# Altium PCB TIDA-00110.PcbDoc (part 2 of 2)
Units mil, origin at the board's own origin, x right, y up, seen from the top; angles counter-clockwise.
Board outline 3543.31 x 1771.65 mil, 4 copper layers (Top Layer, L2_GND-PLANE, L3_PWR-PLANE, Bottom Layer), stack 90 mil thick; 191 components, 98 nets, 449 pads, 138 vias.
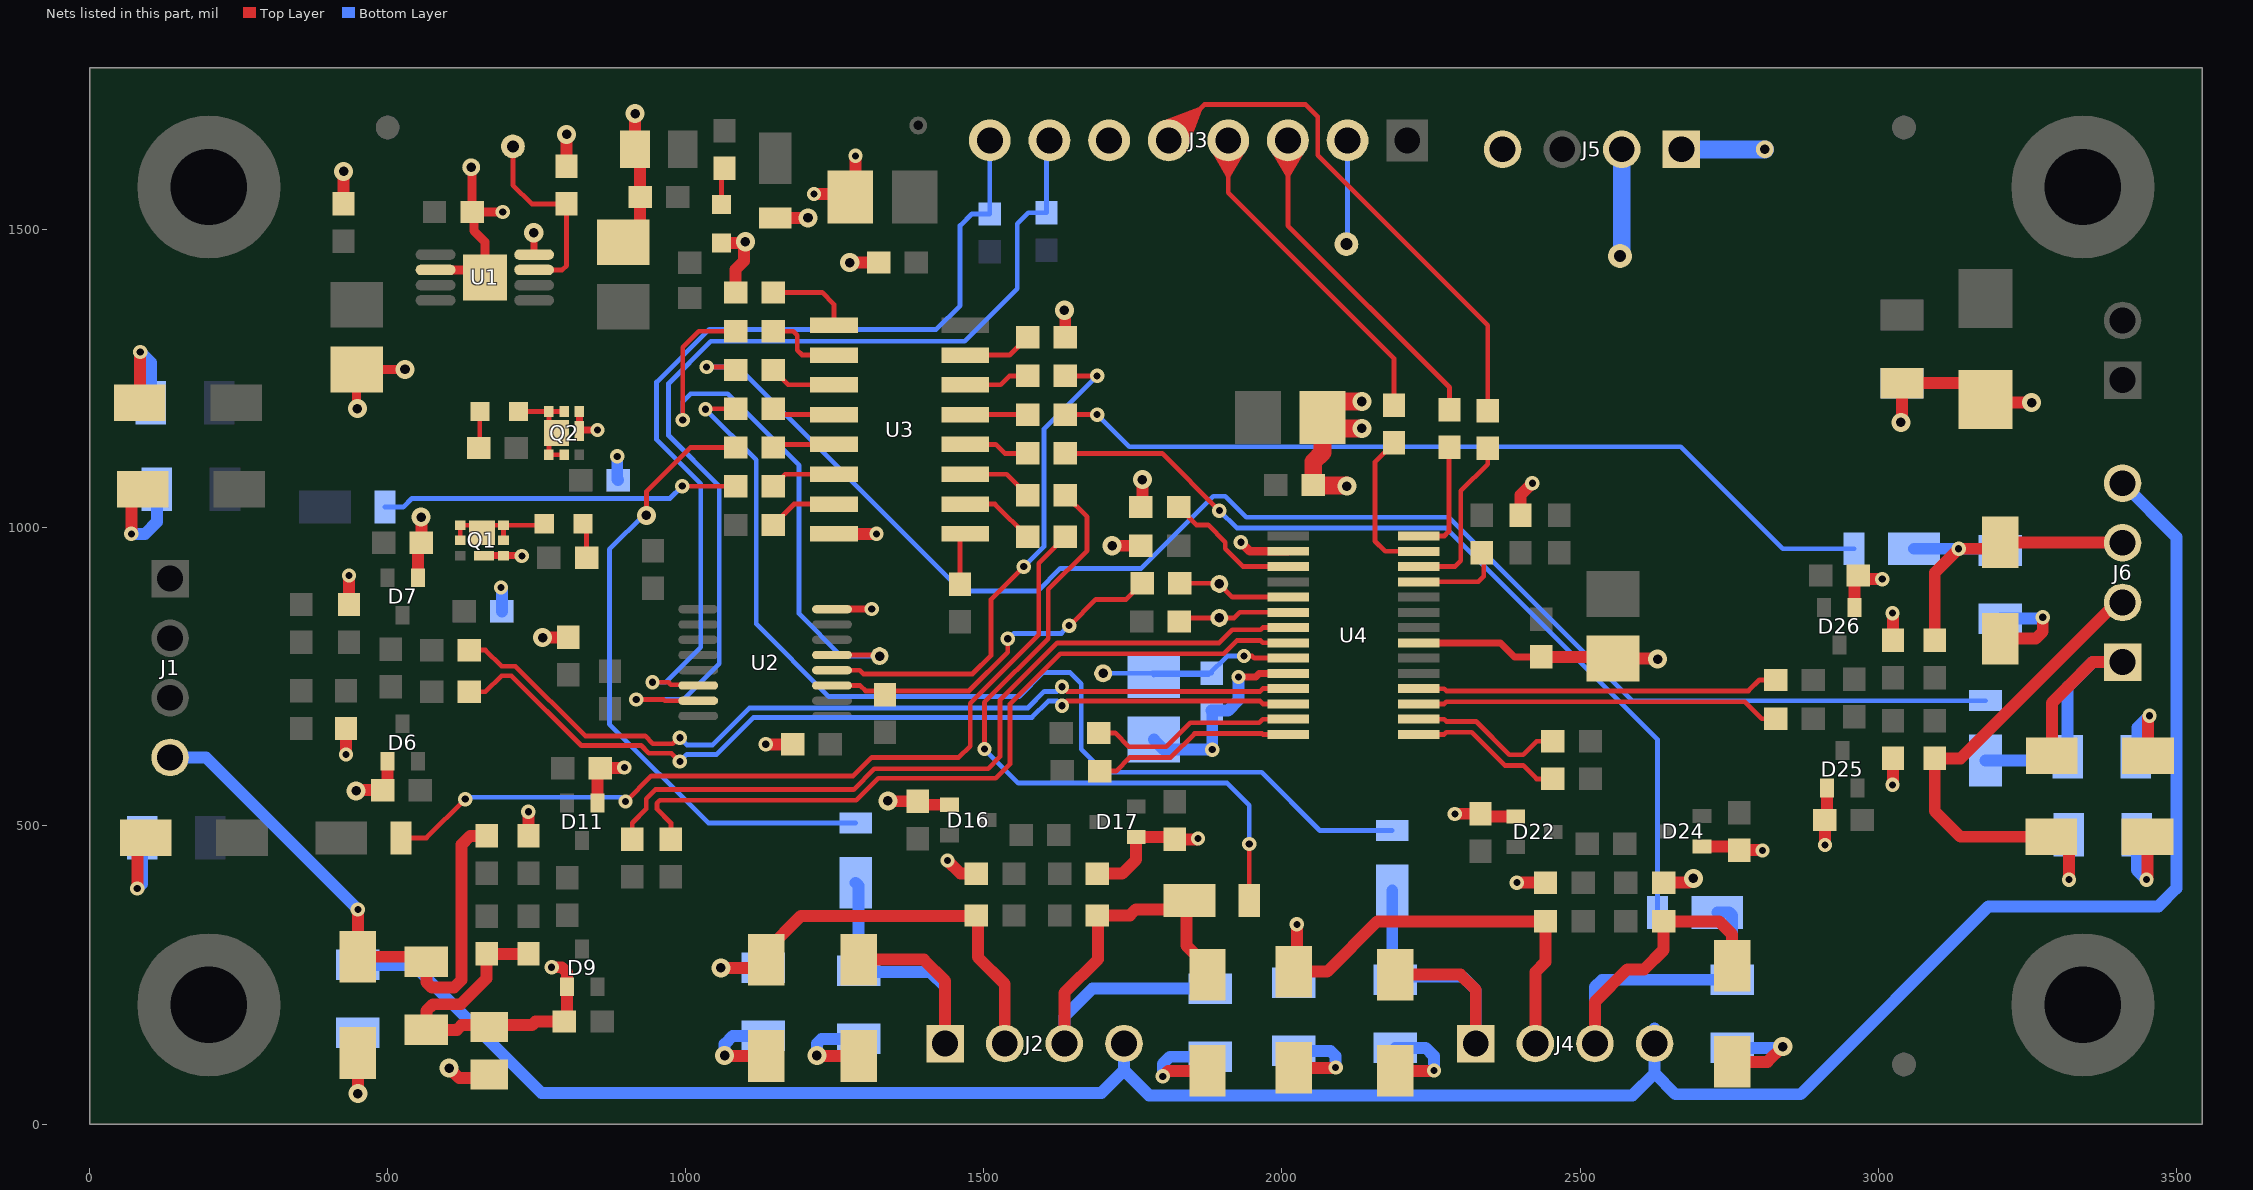
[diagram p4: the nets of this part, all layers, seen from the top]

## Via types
v1: diameter 24, hole 12, Top Layer to Bottom Layer, tented both sides, 92 vias
v2: diameter 32, hole 16, Top Layer to Bottom Layer, tented both sides, 45 vias
v3: diameter 36, hole 16, Top Layer to Bottom Layer, tented both sides, 1 vias

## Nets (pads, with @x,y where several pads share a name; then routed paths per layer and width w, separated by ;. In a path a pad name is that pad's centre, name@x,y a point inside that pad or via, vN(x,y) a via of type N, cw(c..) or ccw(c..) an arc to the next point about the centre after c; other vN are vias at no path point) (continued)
NetC46_1: C46.1 D12.2 J2.2 R28.2 | length 778.8
  Top Layer w20: v2(1059,262) 1121.29,262 D12.2@1135,275.71 1135,291 1193,349 1488.5,349 1490,347.5 1490,280 1535,235 J2.2@1535,135
  Bottom Layer w20: v2(1059,262) 1059.09,262.09 C46.1@1130,262.09
NetC47_2: C47.2 D15.1 D32.1 J2.1 | length 665.8
  Top Layer w20: D15.1@1290,275.71 1399.29,275.71 1435,240 J2.1@1435,135
  Bottom Layer w20: D32.1@1285,404.8 1290,399.8 C47.2@1290,257.09 1292.09,255 1410,255 1435,230 J2.1@1435,135
NetC48_1: C48.1 C50.1 TP5.1 U4.9 | length 427
  Top Layer w8: v1(1936.45,785) 1950,785 1953.4,781.6 U4.9@2010.5,781.6
  Bottom Layer w8: TP5.1@1700,756 C48.1@1782.13,756 ; C48.1@1785,753.13 C48.1@1784,754.13 ; C50.1@1882,756.5 1782.63,756.5 C48.1@1782.13,756 ; v1(1936.45,785) 1908,785 1877.13,754.13 C48.1@1784,754.13 ; C48.1@1782.13,756 C48.1@1784,754.13
NetC49_2: C49.2 D18.1 D19.1 J2.3 R30.2 | length 820.2
  Top Layer w20: J2.3@1635,135 1635,220 1691.5,276.5 R30.2@1691.5,350 ; R30.2@1690.5,350 R30.2@1691.5,350 ; D18.1@1839.8,365 D18.1@1839.8,352.2 ; D19.1@1875,264 1839.8,299.2 D18.1@1839.8,352.2 ; R30.2@1691.5,350 1745,350 1755,360 1832,360 D18.1@1839.8,352.2
  Bottom Layer w20: J2.3@1635,135 1635,180 1682.09,227.09 C49.2@1880,227.09
NetC51_1: C51.1 D20.2 J4.2 R45.2 | length 825.3
  Top Layer w20: v1(2025,335) 2025,260.71 D20.2@2020,255.71 2075.71,255.71 2160,340 R45.2@2442.01,340 2442.01,272.01 2425,255 J4.2@2425,160
  Bottom Layer w20: C51.1@2020,237.09 2025,242.09 v1(2025,335)
NetC53_2: C53.2 D21.1 D33.1 J4.1 | length 576.6
  Top Layer w20: D21.1@2190,250.71 2299.29,250.71 2325,225 J4.1@2325,160
  Bottom Layer w20: D33.1@2185,391.8 2185,247.09 C53.2@2190,242.09 2190,247.09 2302.91,247.09 2325,225 J4.1@2325,160
NetC54_2: C54.2 D23.1 D34.1 J4.3 R51.2 | length 860.2
  Top Layer w20: J4.3@2525,160 2525,205 2579.5,259.5 2607.5,259.5 2640,292 R51.2@2640,340 2733,340 2755,318 D23.1@2755,265.71
  Bottom Layer w20: J4.3@2525,160 2525,230 2537.09,242.09 C54.2@2755,242.09 2755,350 2750,355 D34.1@2730.2,355
NetC56_2: C56.2 D30.1 D35.1 J6.3 R55.2 | length 591.7
  Top Layer w20: R55.2@3095,811.5 3095,925 v1(3135,965) 3194.29,965 D30.1@3205,975.71 3409.29,975.71 J6.3@3410,975
  Bottom Layer w20: D35.1@3060.2,965 v1(3135,965) C56.2@3202.09,965
NetC57_1: C57.1 D27.2 J6.2 R54.2 | length 897.6
  Top Layer w20: v1(3320,410) 3320,475 3313,482 D27.2@3290.29,482 3138,482 3095,525 R54.2@3095,613.5 3138.5,613.5 3400,875 J6.2@3410,875
  Bottom Layer w20: C57.1@3319.91,485 3319.91,410.09 v1(3320,410)
NetC58_2: C58.2 D28.1 D36.1 J6.1 | length 602.4
  Top Layer w20: D28.1@3291.29,618 3291.29,706.29 3360,775 J6.1@3410,775
  Bottom Layer w20: D36.1@3180,609.8 3311.72,609.8 C58.2@3317.91,616 3317.91,732.91 3360,775 J6.1@3410,775
NetD8_1: D8.1 Q2.1 Q2.2 Q2.5 Q2.6 Q2.8 | length 166.9
  Top Layer w8: D8.1@719.8,1195.32 Q2.6@770.41,1195.32 ; Q2.8@770.41,1146.2 Q2.1@770.41,1122.68 Q2.2@796,1122.68 ; Q2.8@783.2,1159 770.41,1171.8 Q2.6@770.41,1195.32 ; Q2.5@796,1195.32 Q2.6@770.41,1195.32
NetD8_2: D8.2 R8.1 | length 59
  Top Layer w8: R8.1@654.52,1136.02 D8.2@654.52,1195
NetD10_1: D10.1 Q1.1 Q1.2 Q1.5 Q1.6 Q1.8 | length 210.4
  Top Layer w8: Q1.2@621.68,979 Q1.1@621.68,1004.59 645.2,1004.59 Q1.8@658,991.8 670.8,1004.59 Q1.6@694.32,1004.59 ; Q1.5@694.32,979 Q1.6@694.32,1004.59 ; D10.1@768.52,1009 764.11,1004.59 Q1.6@694.32,1004.59
NetD10_2: D10.2 R12.1 | length 59
  Top Layer w8: R12.1@833.5,950 D10.2@833.5,1008.98
NetD13_2: D13.2 R26.1 | length 63.1
  Top Layer w8: D13.2@1060,1542.48 1060,1598.5 R26.1@1065,1603.5
NetJ3_2: J3.2 TP8.1 | length 174.8
  Bottom Layer w8: TP8.1@2108,1476 2110,1478 J3.2@2110,1650
NetJ5_1: J5.1 TP10.1 | length 140
  Bottom Layer w30: J5.1@2670,1635 TP10.1@2810,1635
NetJ5_2: J5.2 TP9.1 | length 180.2
  Bottom Layer w30: TP9.1@2567,1456 2570,1459 J5.2@2570,1635
NetR14_2: R14.2 TP1.1 U1.3 | length 328.9
  Top Layer w8: TP1.1@710,1640 710,1575 741.5,1543.5 R14.2@800,1543.5 800,1440 792.8,1432.8 U1.3@745.68,1432.8
NetR19_2: R19.2 U3.6 | length 110.3
  Top Layer w8: R19.2@1146.5,1070 1166.5,1090 U3.6@1248.5,1090
NetR20_2: R20.2 U3.5 | length 104.1
  Top Layer w8: R20.2@1146.5,1135 1151.5,1140 U3.5@1248.5,1140
NetR21_2: R21.2 U3.4 | length 106.2
  Top Layer w8: R21.2@1146.5,1200 1156.5,1190 U3.4@1248.5,1190
NetR22_2: R22.2 U3.3 | length 112.4
  Top Layer w8: R22.2@1146.5,1265 1171.5,1240 U3.3@1248.5,1240
NetR23_2: R23.2 U3.2 | length 133.2
  Top Layer w8: R23.2@1146.5,1330 1180,1330 1187,1323 1187,1298 1195,1290 U3.2@1248.5,1290
NetR24_2: R24.2 U3.7 | length 116.5
  Top Layer w8: R24.2@1146.5,1005 1181.5,1040 U3.7@1248.5,1040
NetR25_1: R25.1 U3.1 | length 145.3
  Top Layer w8: R25.1@1146.5,1395 1228.5,1395 1248.5,1375 U3.1@1248.5,1340
NetR29_1: R29.1 U3.9 | length 85.2
  Top Layer w8: R29.1@1460,905.5 1460,957 U3.9@1460,981.5 ; U3.9@1468.5,990 U3.9@1475,983.5
NetR33_1: R33.1 U3.10 | length 127.8
  Top Layer w8: U3.10@1468.5,1040 1518.5,1040 R33.1@1573.5,985
NetR34_1: R34.1 U3.11 | length 119.5
  Top Layer w8: U3.11@1468.5,1090 1538.5,1090 R34.1@1573.5,1055
NetR35_1: R35.1 U3.12 | length 111.2
  Top Layer w8: U3.12@1468.5,1140 1520,1140 1535,1125 R35.1@1573.5,1125
NetR36_1: R36.1 U3.13 | length 105
  Top Layer w8: U3.13@1468.5,1190 R36.1@1573.5,1190
NetR37_1: R37.1 U3.14 | length 111.2
  Top Layer w8: U3.14@1468.5,1240 1528,1240 1543,1255 R37.1@1573.5,1255
NetR38_2: R38.2 U3.15 | length 117.4
  Top Layer w8: U3.15@1468.5,1290 1543.5,1290 R38.2@1573.5,1320
NetR39_2: R39.2 TP6.1 U4.6 | length 189.4
  Top Layer w8: R39.2@1827.5,843 1833.5,849 TP6.1@1895,849 1920,849 1929.4,858.4 U4.6@2010.5,858.4
NetR40_2: R40.2 TP7.1 U4.5 | length 191.5
  Top Layer w8: R40.2@1828.5,907 1894,907 TP7.1@1895,906 1917,884 U4.5@2010.5,884
NetR41_1: R41.1 U4.3 | length 231.8
  Top Layer w8: R41.1@1826.5,1035 1856.5,1005 1876,1005 1905,976 1905,965 1934.8,935.2 U4.3@2010.5,935.2
NetR42_1: R42.1 U4.25 | length 152.7
  Top Layer w8: U4.25@2229.5,909.5 2289.5,909.5 2329.5,909.5 2338.5,918.5 R42.1@2338.5,958.5
NetR43_1: R43.1 U4.27 | length 258.4
  Top Layer w8: R43.1@2188,1142.5 2156,1110.5 2156,978 2173.3,960.7 U4.27@2229.5,960.7
NetR44_1: R44.1 U4.28 | length 195.6
  Top Layer w8: U4.28@2229.5,986.4 2272.4,986.4 2280,994 2280,1134.5 R44.1@2281,1135.5
NetR47_1: R47.1 U4.26 | length 281.7
  Top Layer w8: U4.26@2229.5,935.1 2290.1,935.1 2300,945 2300,1062 2345,1107 R47.1@2345,1133.5
RATIO: C43.2 D4.1 J1.4 J2.4 J4.4 J6.4 R3.2 R10.2 | length 5280.8
  Top Layer w20: v1(450,360) D4.1@450,280.71 556.38,280.71 R3.2@565,272.09 565,238 574,229 611,229 624,242 624,469 638.5,483.5 R10.2@666,483.5 ; J6.4@3400,1075 J6.4@3410,1075
  Bottom Layer w20: J1.4@135,615 195,615 v1(450,360) C43.2@450,267.09 542.91,267.09 757.68,52.32 1697.32,52.32 1735,90 ; J2.4@1735,135 1735,90 ; J4.4@2625,160 2625,85 ; J6.4@3410,1075 3500.31,984.69 3500.31,395.31 3470,365 3185,365 2870,50 2660,50 2625,85 ; 1735,90 1777,48 2588,48 2625,85
RESET1: R27.1 R40.1 U2.3 | length 612.1
  Top Layer w8: U2.3@1245.2,735.61 1292.39,735.61 1301.5,726.5 1475.05,726.5 1540,791.45 v1(1540,814) ; v1(1643,836) 1644,836 1688,880 1738.5,880 R40.1@1765.5,907
  Bottom Layer w8: v1(1540,814) 1541,814 1550,823 1630,823 v1(1643,836)
RTD1_IEXC1: D31.2 R19.1 | length 602.8
  Top Layer w8: v1(994,1070) R19.1@1083.5,1070
  Bottom Layer w8: D31.2@495.2,1035 526,1035 540.3,1049.3 973.3,1049.3 v1(994,1070)
RTD1_IEXC2: D5.2 R33.2 | length 1436.6
  Top Layer w8: D5.2@522.2,480 565,480 v1(630,545) ; v1(899,541) 942,584 1281,584 1312,615 1458,615 1477,634 1477,705.82 1592.09,820.91 1592.09,940.59 R33.2@1636.5,985
  Bottom Layer w8: v1@634,549 635,548 892,548 v1(899,541)
RTD2_IEXC1: D32.2 R20.1 | length 1083.5
  Top Layer w8: v2(934,1021) 934,1061 1008,1135 R20.1@1083.5,1135
  Bottom Layer w8: v2(934,1021) 934,1022 932,1024 872,964 872,671 1037.8,505.2 D32.2@1285,505.2
RTD2_IEXC2: D18.2 R34.2 | length 1155.4
  Top Layer w8: v1(1501,629) 1501,707.2 1608.09,814.28 1608.09,897.09 1673,962 1673,1018.5 R34.2@1636.5,1055 ; D18.2@1945.2,375 v1(1945.2,469.8)
  Bottom Layer w8: v1(1501,629) 1558,572 1908,572 1945.2,534.8 v1(1945.2,469.8)
RTD3_IEXC1: D33.2 R21.1 | length 1754.8
  Top Layer w8: v1(1033,1199) 1034,1200 R21.1@1083.5,1200
  Bottom Layer w8: v1(1033,1199) 1118,1114 1118,839 1240,717 1559,717 1599.6,757.6 1644.4,757.6 1663.4,738.6 1663.4,628.6 1702,590 1966,590 2063.8,492.2 D33.2@2185,492.2
RTD3_IEXC2: D34.2 R35.2 | length 1482.2
  Top Layer w8: R35.2@1636.5,1125 1799,1125 v1(1895,1029)
  Bottom Layer w8: v1(1895,1029) 1924,1000 2275,1000 2629.8,645.2 D34.2@2629.8,355
RTD4_IEXC1: D36.2 R22.1 | length 2559.2
  Top Layer w8: v1(1035,1270) 1078.5,1270 R22.1@1083.5,1265
  Bottom Layer w8: v1(1035,1270) 1087,1270 1463,894 1590,894 1628,932 1764,932 1885,1053 1904.94,1053 1939.94,1018 2279.63,1018 2587.43,710.2 D36.2@3180,710.2
RTD4_IEXC2: D35.2 R36.2 | length 1416.5
  Top Layer w8: R36.2@1636.5,1190 v1(1690,1190)
  Bottom Layer w8: v1(1690,1190) 1744,1136 2669,1136 2840,965 D35.2@2959.8,965
RTD_AINN1: R6.1 U4.12 | length 1495.5
  Top Layer w8: R6.1@636.5,725 664,725 691,752 707.54,752 824.54,635 925,635 938,622 976,622 v1(990,608) ; v1(1631,701.6) 1639,709.6 1963.2,709.6 1968,704.8 U4.12@2010.5,704.8
  Bottom Layer w8: v1(990,608) 1002,620 1051.63,620 1113.63,682 1580.63,682 1608.23,709.6 1623,709.6 v1(1631,701.6)
RTD_AINN2: R31.1 U4.14 | length 342.7
  Top Layer w8: R31.1@1694.5,592 1722,592 1745,615 1813.46,615 1853.46,655 1966.6,655 1968,653.6 U4.14@2010.5,653.6
RTD_AINN3: R49.1 U4.16 | length 259
  Top Layer w8: U4.16@2229.5,679.1 2272,679.1 2275.8,675.3 2325.46,675.3 2381.26,619.5 2404.5,619.5 2427,642 R49.1@2454.5,642
RTD_AINN4: R53.1 U4.18 | length 608.2
  Top Layer w8: U4.18@2229.5,730.3 2272,730.3 2275.8,726.5 2782.5,726.5 2801,745 R53.1@2828.5,745
RTD_AINP1: R5.1 U4.11 | length 1493.9
  Top Layer w8: R5.1@636.5,795 664,795 691,768 714.17,768 831.17,651 931.63,651 944.63,638 978,638 988,648 v1(990,648) ; v1(1631,733.6) 1639,725.6 1963.2,725.6 1968,730.4 U4.11@2010.5,730.4
  Bottom Layer w8: v1(990,648) 1002,636 1045,636 1107,698 1574,698 1601.6,725.6 1623,725.6 v1(1631,733.6)
RTD_AINP2: R32.1 U4.13 | length 346.7
  Top Layer w8: R32.1@1692.5,656 1720,656 1743,633 1806,633 1846,673 1961.8,673 1968,679.2 U4.13@2010.5,679.2
RTD_AINP3: R48.1 U4.15 | length 259
  Top Layer w8: U4.15@2229.5,653.5 2272,653.5 2275.8,657.3 2318,657.3 2373.8,601.5 2404.5,601.5 2427,579 R48.1@2454.5,579
RTD_AINP4: R52.1 U4.17 | length 612.4
  Top Layer w8: U4.17@2229.5,704.7 2272,704.7 2275.8,708.5 2776.5,708.5 2805,680 R52.1@2828.5,680
RTD_REFN0: R17.1 U4.8 | length 1303
  Top Layer w8: R17.1@975,477.5 975,505 951.5,528.5 951.5,538 956.5,543 1286,543 1323,580 1520,580 1544,604 1544,704.94 1628.06,789 1902,789 1924,811 1964.2,811 1968,807.2 U4.8@2010.5,807.2
RTD_REFP0: R15.1 U4.7 | length 1329.1
  Top Layer w8: R15.1@910,477.5 910,505 933.5,528.5 933.5,545.46 949.04,561 1281.37,561 1316.37,596 1507,596 1527,616 1527,710.57 1623.43,807 1894.54,807 1916.54,829 1964.2,829 1968,832.8 U4.7@2010.5,832.8
RTD_SEL0: R37.2 U2.4 | length 878.4
  Top Layer w8: U2.4@1245.2,761.2 1291.8,761.2 1298,755 1480.92,755 1512,786.08 1512,880 v1(1567,935) ; R37.2@1636.5,1255 v1(1690,1255)
  Bottom Layer w8: v1(1567,935) 1601,969 1601,1166 v1(1690,1255)
RTD_SEL1: R23.1 TP3.1 U2.5 | length 1000.3
  Top Layer w8: v1(995,1181) 995,1303 1022,1330 R23.1@1083.5,1330 ; U2.5@1245.2,786.8 1323.2,786.8 TP3.1@1325,785
  Bottom Layer w8: v1(995,1181) 995,1212 1008,1225 1070,1225 1190,1105 1190,856 1261,785 TP3.1@1325,785 ; TP3.1@1332.5,790.5 TP3.1@1335,788
SCL: J3.8 R56.1 U2.14 | length 1537.5
  Top Layer w8: v1(944,741) 971,741 975,737 1019.41,737 U2.14@1020.8,735.61
  Bottom Layer w8: v1(944,741) 966,741 1025,800 1025,1074 951,1148 951,1244.63 1039.37,1333 1420,1333 1460,1373 1460,1507 1479.5,1526.5 R56.1@1510,1526.5 J3.8@1510,1650
SCLK: J3.3 R44.2 | length 1036.1
  Top Layer w8: J3.3@1980.05,1641.84 2010,1590.96 ; J3.3@1987.4,1645.5 2010,1590.96 ; J3.3@1995.08,1648.08 2010,1590.96 ; J3.3@2002.97,1649.58 2010,1590.96 ; J3.3@2010,1650 2010,1507 2281,1236 R44.2@2281,1198.5 ; J3.3@2017.03,1649.58 2010,1590.96 ; J3.3@2024.92,1648.08 2010,1590.96 ; J3.3@2032.6,1645.5 2010,1590.96 ; J3.3@2039.95,1641.84 2010,1590.96
SDA: J3.7 R57.1 U2.15 | length 1713.8
  Top Layer w8: v1(917,712) 963.02,712 965,710.02 U2.15@1020.8,710.02
  Bottom Layer w8: v1(917,712) 996,712 1056,772 1056,1070 971,1155 971,1242 1042,1313 1468,1313 1556,1401 1556,1510 1574.5,1528.5 R57.1@1605,1528.5 1605,1645 J3.7@1610,1650
SDI: J3.5 R47.2 | length 1483.1
  Top Layer w8: J3.5@1793.18,1676.09 1862.01,1702.01 ; J3.5@1796.46,1668.64 1862.01,1702.01 ; J3.5@1800.51,1661.67 1862.01,1702.01 ; J3.5@1805.27,1655.21 1862.01,1702.01 ; J3.5@1810,1650 1870,1710 2040,1710 2060,1690 2060,1625 2345,1340 R47.2@2345,1196.5 ; J3.5@1815.21,1645.27 1862.01,1702.01 ; J3.5@1821.67,1640.51 1862.01,1702.01 ; J3.5@1828.64,1636.46 1862.01,1702.01 ; J3.5@1836.09,1633.18 1862.01,1702.01
SDO: J3.4 R43.2 | length 1032
  Top Layer w8: J3.4@1880.05,1641.84 1910,1590.96 ; J3.4@1887.4,1645.5 1910,1590.96 ; J3.4@1895.08,1648.08 1910,1590.96 ; J3.4@1902.97,1649.58 1910,1590.96 ; J3.4@1910,1650 1910,1562 2188,1284 R43.2@2188,1205.5 ; J3.4@1917.03,1649.58 1910,1590.96 ; J3.4@1924.92,1648.08 1910,1590.96 ; J3.4@1932.6,1645.5 1910,1590.96 ; J3.4@1939.95,1641.84 1910,1590.96
SGND: C2.2 C3.1 C4.2 C5.2 C6.2 C7.2 C8.1 C9.2 C10.1 C11.2 C13.2 C14.2 C15.1 C16.2 C17.2 C18.2 C19.2 C20.2 C21.1 C22.2 C24.2 C25.2 C26.2 C27.2 C28.1 C29.2 C31.2 C32.2 C33.2 C35.2 C36.2 C37.1 C38.2 C44.2 C45.2 C48.2 C50.2 C52.2 D6.1 D7.1 D9.1 D11.1 D13.1 D14.2 D16.1 D17.1 D22.1 D24.1 D25.1 D26.1 J3.6 J5.4 Q1.4 Q1.7 Q2.4 Q2.7 R3.1 R4.2 R9.2 R11.1 R14.1 R25.2 R38.1 R41.2 R46.1 TP2.1 U1.4 U1.6 U1.9 U2.8 U3.8 U4.2 U4.10 U4.21 | length 5008.7
  Top Layer w12: Q1.7@661.78,953.41 Q1.4@694.32,953.41 717.59,953.41 724,947 725,948 v1(725,953) ; v2(745,1495) 745.68,1494.32 U1.4@745.68,1458.39 ; Q2.7@821.59,1162.78 Q2.4@821.59,1195.32 ; Q2.7@822.59,1164.32 v1(852,1164.32) v1@855.68,1164.32 ; C14.2@893.39,1458.39 C14.2@900,1465 ; U2.8@1245.2,863.57 1245.64,864 v1(1312,864) ; v1(1927,750) 1956,750 1962,756 U4.10@2010.5,756 ; U4.21@2229.5,807.1 2366.4,807.1 2390,783.5 C29.2@2435,783.5
  Top Layer w15: v2(449,1200) 448,1201 C4.2@448,1265.87 528.87,1265.87 v2(529,1266) ; U1.6@580.32,1432.8 U1.9@650.2,1432.8 ; C8.1@641.5,1530 641.5,1596.5 TP2.1@645,1600 ; U1.9@663,1420 663,1480 644.5,1498.5 644.5,1530 v1(693,1530) ; v1(1931,976) 1946.2,960.8 U4.2@2010.5,960.8
  Top Layer w20: C5.2@426,1543.5 v2(426,1598) ; v1(430,620) C2.2@430,663.5 ; C3.1@435,871.5 v1(435,920) ; v2(447,559) 448,560 C6.2@491.5,560 499.41,567.91 D6.1@499.41,608.5 ; D7.1@550.59,916.5 C7.2@550.59,969.09 ; v2(556,1018) 556.5,1017.5 C7.2@556.5,975 ; C9.2@736,285.5 R4.2@666,285.5 666,244.4 622.6,201 576,201 565,190 R3.1@565,157.91 615.91,157.91 624,166 742,166 748,172 C11.2@796.5,172 ; C10.1@736,483.5 v1(736,524) ; v2(760,816) 760.5,816.5 R11.1@803,816.5 ; v1(775,263) 792,263 800.41,254.59 D9.1@800.41,230.5 C11.2@800.41,175.91 ; R14.1@800,1606.5 v2(800,1660) ; D11.1@851.59,538.5 C13.2@851.59,592.09 ; C13.2@856.5,597 896,597 v1(897,598) ; C14.2@895,1479.13 923.5,1507.64 C15.1@923.5,1555 923.5,1626.5 C16.2@915,1635 v2@915,1690 ; D13.1@1055,1477.52 D13.1@1060,1477.52 1097.52,1477.52 1097.52,1447.52 1083.5,1433.5 R25.2@1083.5,1395 ; v1(1134,637) C17.2@1179.5,637 ; D14.2@1150,1519.8 1204.8,1519.8 v2(1205,1520) ; v1(1215,1560) 1248,1560 1250,1558 1284.87,1558 1284.87,1623.87 v1(1284.73,1624) ; U3.8@1248.5,990 v1(1320,990) ; v2(1275,1445) C19.2@1323.5,1445 ; v2(1339,542) 1339.5,541.5 C18.2@1389,541.5 ; C18.2@1394.91,535.59 D16.1@1442.5,535.59 ; v1(1439,442) 1461,420 C21.1@1487.5,420 ; v2(1635,1365) 1636.5,1363.5 R38.1@1636.5,1320 ; C22.2@1690.5,420 1732,420 1755.5,443.5 D17.1@1755.5,481.41 1816.09,481.41 C24.2@1820,477.5 1857.5,477.5 v1(1859,479) ; v2(1715,970) C25.2@1763.5,970 ; R41.2@1763.5,1035 1766,1037.5 v2(1766,1081) ; v1(2290,520) 2290.5,520.5 C27.2@2333,520.5 2337.91,515.59 D22.1@2392.01,515.59 ; v1(2394,405) C28.1@2442.01,405 ; R46.1@2400,1021.5 2400,1055 v1(2420,1075) ; C29.2@2435,783.5 C31.2@2552.36,783.5 ; C31.2@2555,780.87 2629.13,780.87 v2(2630,780) ; C32.2@2640,405 2683,405 v2(2690,412) ; D24.1@2704.5,465.41 C33.2@2761.09,465.41 ; C33.2@2767,459.5 2805.5,459.5 v1(2806,459) ; C35.2@2910.5,510 2910.5,468.5 v1(2911,468) ; C35.2@2914.41,513.91 D25.1@2914.41,563.5 ; D26.1@2960.59,866.5 2960.59,914.09 2960.68,914 v1(3007,914) ; v1(3024,569) 3025,568 C37.1@3025,613.5 ; v1(3024,857) 3025,856 C38.2@3025,811.5
  Top Layer w30: v2(2109,1070) 2108,1071 2052.5,1071 C52.2@2052.5,1072 2052.5,1111 2068.13,1126.64 C26.2@2068.13,1185 ; v2(2134,1167) 2086.13,1167 C26.2@2068.13,1185 ; v2(2134,1212) 2095.13,1212 C26.2@2068.13,1185
  Bottom Layer w20: v1(690,900) 691.5,898.5 C44.2@691.5,860 ; v1(885,1120) 885,1081.5 C45.2@886.5,1080 ; C48.2@1785,644.87 1801.87,628 v1(1883,628) C50.2@1883,693.5 ; C50.2@1882,693.5 C50.2@1883,693.5 ; v1(1927,750) 1927,711 1909.5,693.5 C50.2@1883,693.5
  other v2: 1100,1480 915,1695
SGND1: C39.1 C40.1 C41.1 C42.2 C43.1 C46.2 C47.1 C49.1 C51.2 C53.1 C54.1 C55.1 C56.1 C57.2 C58.1 D1.2 D2.2 D3.1 D4.2 D12.1 D15.2 D19.2 D20.1 D21.2 D23.2 D27.1 D28.2 D29.1 D30.2 R9.1 | length 2646.2
  Top Layer w20: v1(70,990) 70,1045.71 D2.2@89.29,1065 ; v1(80,395) 80,465.71 D1.2@94.29,480 ; D3.1@84.29,1210 84.29,1294.29 v1(85,1295) ; v2(450,51) 449,52 449,58 450,59 D4.2@450,119.29 ; v2(603,94) 620,77 652,77 R9.1@670,95 ; v2(1065,115) 1065.71,114.29 D12.1@1135,114.29 ; v2(1220,115) 1220.71,114.29 D15.2@1290,114.29 ; v1(1800,80) 1809.29,89.29 D19.2@1875,89.29 ; D20.1@2020,94.29 2089.29,94.29 v1(2090,95) ; D21.2@2190,89.29 2254.29,89.29 v1(2255,90) ; D23.2@2755,104.29 2814.29,104.29 v2(2840,130) ; v2@3040,1179 C39.1@3040,1242.91 3152.44,1242.91 D29.1@3180,1215.35 3185.31,1210.04 v2(3257.56,1210.04) ; D30.2@3205,814.29 3264.29,814.29 3276.14,826.14 v1(3276.14,850) ; v1(3450,410) 3451.71,411.71 D27.1@3451.71,482 ; D28.2@3452.71,618 3452.71,682.71 v1(3455,685)
  Bottom Layer w20: v1(70,990) 93,990 112.91,1009.91 C41.1@112.91,1065 ; v1(80,395) 87.91,402.91 C40.1@87.91,480 ; v1(85,1295) 102.91,1277.09 C42.2@102.91,1210 ; v2(450,51) C43.1@450,152.91 ; v2(1065,115) 1065,134.09 1078.83,147.91 C46.2@1130,147.91 ; v2(1220,115) 1220,135 1227.91,142.91 C47.1@1290,142.91 ; v1(1800,80) 1800,101 1811.91,112.91 C49.1@1880,112.91 ; C51.2@2020,122.91 2081.09,122.91 2090,114 v1(2090,95) ; C53.1@2190,127.91 2241.09,127.91 2255,114 v1(2255,90) ; C54.1@2755,127.91 2837.91,127.91 v2(2840,130) ; v2(3038,1177) 3040,1179 C55.1@3040,1242.91 ; C56.1@3205,847.91 3274.06,847.91 v1(3276.14,850) ; C58.1@3432.09,616 3435,618.91 3435,665 v1(3455,685) ; C57.2@3434.09,485 3434.09,425.91 v1(3450,410)
pads on no net: FID1.1 FID2.1 FID3.1 FID4.1 FID5.1 FID6.1 H1.1 H2.1 H3.1 H4.1 J3.1 U1.2

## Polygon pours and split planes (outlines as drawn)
SGND1 on L2_GND-PLANE "Bottom Layer-No Net" (solid, remove dead copper, pour order 24): 20,20 3508.31,20 3523.31,35 3523.31,1725 3510,1730 3505,1735 3220,1735 3200,1715 3200,240 3190,230 395,230 385,240 385,1710 355,1740 45,1740 20,1715
SGND on L2_GND-PLANE "Bottom Layer-No Net" (solid, remove dead copper, pour order 20): 405,242 1136,243 1501,244 1986,245 2740,246 3187,246 3191,251 3191,1724 3163.35,1751.65 415,1751.65 395,1730 392,255
GND_EARTH on Top Layer "Bottom Layer-No Net" (solid, pour order 8): 3240,1320 3345,1215 3475,1215 3500,1240 3500,1415 3475,1440 2980,1440 2965,1425 2965,1330 2975,1320
+3.3V on L3_PWR-PLANE "Bottom Layer-No Net" (solid, remove dead copper, pour order 6): 3030,1651.65 3185,1651.65 3361.65,1651.65 3423.31,1590 3423.31,1435 3423.31,1195 3423.31,240 3423.31,173.31 3380,130 3370,120 3255,120 195,120 145,170 120,195 120,290 120,1570 201.65,1651.65 205,1651.65 345,1651.65

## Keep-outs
Keep-Out Layer:
  lines w10: 20,20 20,1751.65 3523.31,1751.65 3523.31,20 20,20
  text ".Layer_Name" at 577,-858.49 h60

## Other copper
Top Layer:
  text ".Layer_Name" at 577,-858.49 h60
L2_GND-PLANE:
  text ".Layer_Name" at 612,-866 h60
L3_PWR-PLANE:
  pour cut-out: 3485,1725 3485,1425 3200,1425 3200,1725
  pour cut-out: 3480,345 3480,38 3200,38 3200,345
  pour cut-out: 340,345 340,35 70,35 70,345
  pour cut-out: 345,1730 345,1425 65,1425 65,1725 60,1730
  text ".Layer_Name" at 640,-860 h60
Bottom Layer:
  text ".Layer_Name" at 577,-858.49 h60

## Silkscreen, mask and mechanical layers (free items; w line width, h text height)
Top Overlay:
  circle w7: c1290,665 r7.07
  circle w7: c745,1345 r11.18
  lines w6: 323,768 463,768 476,781 ; 662,1236 674,1236 ; 688,1236 705,1236 ; 690,1223 690,1249.3 ; 747,1043 764,1043 ; 762,1029.7 762,1056 ; 778,1043 790,1043 ; 1718.98,392.8 1745,366.78 1745,333 ; 2863.5,793.5 2875,782 2923,782 2925.72,782 ; 675,1225 675,1249 687,1237 675,1225 ; 765,1042 777,1030 777,1054 765,1042
  lines w7: 395,920 395,912.78 407.8,899.98 ; 461,919 470,910 477,910 ; 1664.98,1082.27 1678,1095.28 1678,1127 1689,1138 1698,1138 ; 1716,1009 1716,1005 1723.8,997.2 1735.02,997.2 ; 1766,564 1766,576 ; 1857,786.3 1881,810.3 1881,818 ; 1900,769 1900,784 1934,818 1934,871 1921,884 ; 1930,285 1955,310 1970,310 2024,364 2039.01,364 ; 1975,365 1995,365 2005,375 2005,380 ; 2080,285 2110,315 2110,360 ; 2362.2,1049.98 2362.2,1077.2 2404,1119 ; 2372.8,1049.98 2372.8,1062.8 2410,1100 2450,1100 2470,1120 ; 2404,1119 2404.01,1119
  lines w10: 591,1035 605,1021
  text ".Layer_Name" at 577,-858.49 h60
Bottom Overlay:
  text "ISE 3016 REV:E1" at 2746,1214 h40
  text "TIDA-00110" at 2749,1146 h40
  text ".Layer_Name" at 577,-858.49 h60
Top Paste:
  text ".Layer_Name" at 577,-858.49 h60
Bottom Paste:
  text ".Layer_Name" at 577,-858.49 h60
Top Solder:
  text ".Layer_Name" at 577,-858.49 h60
  text ".Layer_Name" at 577,-858.49 h60
Bottom Solder:
  text ".Layer_Name" at 577,-858.49 h60
Drill Guide:
  text ".Layer_Name" at 577,-858.49 h60
M1 Board Outline:
  the board outline again, w10
  text "outline" at 570.5,-862.49 h60
M2 Board Dimensions:
  rectangle: 124.5,-410.5 499.5,-285.5
  rectangle: -0.5,-285.5 124.5,-160.5
  lines w7: -0.5,-285.5 999.5,-285.5 ; 124.5,-410.5 124.5,-160.5 ; 249.5,-410.5 249.5,-160.5 ; 499.5,-410.5 499.5,-160.5 ; 749.5,-410.5 749.5,-160.5 ; -0.5,-410.5 -0.5,-160.5 999.5,-160.5 999.5,-410.5 -0.5,-410.5
  lines w7.87: 0,25 3780,25 ; 0,1960 3780,1960 ; 50,45 50,2000 ; 1645,1420 1830,1420 1870,1460 1870,1680 2010,1820 2345,1820 2370,1795 2370,960 2415,915 2655,915 2700,870 2700,225 2715,210 2760,210 2775,225 2775,925 2820,970 2880,1030 3045,1030 3150,1030 3245,1125 3475,1125 3490,1110 3745,1110 ; 2615,1230 2710,1230 2725,1245 2725,1805 2745,1825 2805,1825 2825,1805 2825,1130 2845,1110 2908.83,1110 2920,1121.17 2920,1160 ; 2685,1230 2520,1230 2500,1250 2500,1860 2480,1880 1595,1880 1575,1860 1575,1570 1645,1500 1645,1265 1625,1245 1465,1245 1450,1260 1450,1920 1490,1960 3110,1960 3110,1245 3090,1225 3045,1225 3035,1235 3035,1858.07 3013.07,1880 2940,1880 2920,1860 2920,1135 ; 3745,0 3745,2000
  lines w10: -0.5,-475.5 -0.5,-455.5 ; 59.5,-485.5 -0.5,-465.5 ; 59.5,-445.5 -0.5,-465.5 ; 223.58,-465.5 -0.5,-465.5 ; 775.42,-465.5 999.5,-465.5 ; 939.5,-485.5 999.5,-465.5 ; 939.5,-445.5 999.5,-465.5 ; 999.5,-475.5 999.5,-455.5
  text "1000 (mil)" at 233.58,-501.49 h60
  text ".Layer_Name" at 577,-858.49 h60
M3 3D STEP Top:
  text ".Layer_Name" at 577,-858.49 h60
M4 3D STEP Bottom:
  text ".Layer_Name" at 577,-858.49 h60
M5 Assembly Top:
  lines w4: 3135,1235 3225,1235 3225,1370 3135,1370 3135,1235
  lines w6: 701,1194 719,1194 ; 733,1178 733,1211 ; 738,1008 752,1008 ; 747,1194 733,1194 ; 752,991 752,1024 ; 766,1008 784,1008 ; 1015,1505 1037,1505 1028,1505 ; 1026,1519 1026,1535 ; 1027,1492 1027,1504 ; 733,1194 720,1207 720,1181 733,1194 ; 752,1008 765,1021 765,995 752,1008 ; 1016,1517 1026,1507 1036,1517 1016,1517
  lines w10: -292,-930.17 6308,-930.17 ; -292,-726.83 6310,-726.83 ; -292,-523.5 -292,-1133.5 3713,-1133.5 6310,-1133.5 6310,-523.5 -291.5,-523.5 -291.5,-1133.5 1284,-1133.5 ; 2173,-1133.5 2173,-523.5 ; 3735,-726 3735,-522.67 ; 4280,-726.83 4280,-523.5 ; 4902,-1140 4902,-937.17
  text "D29" at 3195,1255 h35 r90
  text "COMPONENTS MARKED 'DNP' SHOULD NOT BE POPULATED." at 1153.5,-318.5 h60
  text "ASSEMBLY VARIANT:" at 1153,-434 h60
  text ".VariantName" at 2189,-434 h60
  text "PCB VIEWED FROM TOP SIDE" at -228.5,-655.67 h60
  text "BOARD #:" at 2248,-655.67 h60
  text "TIDA-00110" at 2793.5,-655.67 h60
  text "SVN REV:" at 4476,-655.67 h60
  text ".VersionControl_RevNumber" at 4982,-655.67 h60
  text "REV: E1" at 3805,-660 h60
  text "ASSEMBLY TOP" at 524.5,-846.49 h60
  text "LAYER NAME=" at -228.5,-858.49 h60
  text "PLOT NAME =" at -228.5,-1064.34 h60
  text ".plot_File_Name" at 577,-1064.34 h60
  text "GENERATED    :" at 2250,-1064.34 h60
  text ".Print_Date" at 3119.5,-1064.34 h60
  text ".Print_Time" at 3848.5,-1064.34 h60
  text "TEXAS INSTRUMENTS" at 5113,-1064.34 h60
M6 Assembly Bottom:
  lines w10: -292.5,-727.33 6309.5,-727.33 ; -290.5,-930.67 6309.5,-930.67 ; 1115.5,-1140.5 1115.5,-937.67 ; 1737.5,-727.33 1737.5,-524 ; 2236,-723 2236,-519.67 ; 3844.5,-1134 3844.5,-524 ; 4733.5,-1134 6309,-1134 6309,-524 -292.5,-524 -292.5,-1134 2304.5,-1134 6309.5,-1134 6309.5,-524
  text "COMPONENTS MARKED 'DNP' SHOULD NOT BE POPULATED." at 6102,-318 h60
  text ".VariantName" at 5058,-434 h60
  text "ASSEMBLY VARIANT:" at 6097,-434 h60
  text "REV: E1" at 2173,-655 h60
  text ".VersionControl_RevNumber" at 1035.5,-656.17 h60
  text "SVN REV:" at 1541.5,-656.17 h60
  text "TIDA-00110" at 3224,-656.17 h60
  text "BOARD #:" at 3769.5,-656.17 h60
  text "PCB VIEWED FROM BOTTOM SIDE" at 6246,-656.17 h60
  text "ASSEMBLY BOTTOM" at 1836.85,-855.49 h60
  text "LAYER NAME=" at 2547.85,-858.49 h60
  text "TEXAS INSTRUMENTS" at 904.5,-1064.84 h60
  text ".Print_Time" at 2169,-1064.84 h60
  text ".Print_Date" at 2898,-1064.84 h60
  text "GENERATED    :" at 3767.5,-1064.84 h60
  text ".plot_File_Name" at 5440.5,-1064.84 h60
  text "PLOT NAME =" at 6246,-1064.84 h60
M9 Title Sheet:
  drawing of 57 lines, arcs and shapes, not listed
  text "1" at 735.36,8048.5 h70
  text "2" at 3231.02,8048.5 h70
  text "3" at 5720.36,8048.5 h70
  text "4" at 8227.03,8048.5 h70
  text "5" at 10726.02,8048.5 h70
  text "6" at 13231.02,8048.5 h70
  text "A" at -420.98,6905.5 h70
  text "A" at 14379.02,6905.5 h70
  text "B" at -420.98,4525.5 h70
  text "B" at 14379.02,4525.5 h70
  text "C" at -420.98,2150.5 h70
  text "C" at 14379.02,2150.5 h70
  text "PROJECT TITLE:" at 11339.02,289.5 h45
  text ".PRJ_Title" at 11464.52,158 h100
  text "DESIGNED FOR:" at 11339.02,-11.5 h45
  text ".PRJ_Customer" at 11389.02,-151.5 h70
  text "D" at -420.98,-219.5 h70
  text "D" at 14379.02,-219.5 h70
  text "FILE NAME:" at 11339.02,-311.5 h45
  text ".PCB_File_Name_No_Path" at 11389.02,-431.5 h70
  text "Texas Instruments (TI) and/or its licensors do not warrant the accuracy or completeness of this specification" at 6369.52,-593.34 h45
  text "ENGINEER:" at 11339.02,-601.5 h45
  text "LAYOUT BY:" at 12844.02,-601.5 h45
  text "or any information contained therein. TI and/or its licensors do not warrant that this design will meet" at 6324.53,-706 h45
  text ".PRJ_Engineer" at 11389.02,-756.49 h70
  text "the specifications, will be suitable for your application or fit for any particular purpose, or will operate in" at 6324.53,-818.67 h45
  text "ALTIUM DESIGNER VERSION:" at 12844.02,-911.5 h45
  text "an implementation. TI and/or its licensors do not warrant that the design is production worthy. You should" at 6324.53,-931.33 h45
  text "completely validate and test your design implementation to confirm the system functionality for your application." at 6369.52,-1044 h45
  text ".print_Scale" at 11389.02,-1044.83 h70
  text ".Application_BuildNumber" at 12894.52,-1044.83 h70
  text "1" at 735.36,-1251.5 h70
  text "2" at 3231.02,-1251.5 h70
  text "3" at 5720.36,-1251.5 h70
  text "4" at 8227.03,-1251.5 h70
  text "5" at 10726.02,-1251.5 h70
  text "6" at 13231.02,-1251.5 h70
M10 Fab Notes:
  drawing of 220 lines, arcs and shapes, not listed
  text "DESIGN INFORMATION" at 12381.02,6810 h60
  text "(REFER ALSO ARRAY/PANEL PROFILING INFORMATION)" at 12019.46,6648.29 h60
  text "BOARD SIZE" at 11333.46,6644 h60
  text "X" at 12301.46,6516.18 h60
  text "1771.653MIL" at 12446,6515 h60
  text "3543.307MIL" at 11713,6511 h60
  text "Number of Layers :" at 11736.46,6319 h60
  text "4" at 12831.27,6309 h60
  text "MIN. TRACK WIDTH:" at 11736.46,6180 h60
  text "8" at 12832.7,6180 h60
  text "MIL" at 12987.46,6180 h60
  text "8" at 12737,6051 h60
  text "MIN. CLEARANCE:" at 11736.46,6048 h60
  text "MIL" at 12987.46,6048 h60
  text "MIN. VIA PAD SIZE:" at 11736.46,5916 h60
  text "24" at 12802.71,5916 h60
  text "MIL" at 12987.46,5916 h60
  text "0.1524mm (6MIL)" at 12431.46,5774.29 h60
  text "EXTERNAL" at 13182,5772 h60
  text "MINIMUM ANNULAR RING" at 11407.23,5770 h60
  text "PER" at 11607.23,5652 h60
  text "IPC-D-275 CLASS 2 LEVEL C" at 11827.23,5652 h60
  text "MIL, HOLES" at 13315.46,5539.71 h60
  text "+/-" at 12923,5539 h60
  text "+/-" at 13777,5539 h60
  text "REGISTRATION TOLERANCES:" at 11407.23,5534 h60
  text "METAL" at 12607,5534 h60
  text "5" at 13183.2,5534 h60
  text "3" at 14016.2,5534 h60
  text "MIL" at 14132.46,5534 h60
  text "MATERIAL:" at 11332.46,5324.54 h60
  text "FR-4 High Tg" at 12318.9,5184.21 h60
  text "X" at 11606.46,5175.64 h60
  text "FR-408" at 11753.46,5175.64 h60
  text "OTHER" at 13241.46,5175.64 h60
  text "63 MIL (1.6mm) +/-10%" at 12073.56,5012.92 h60
  text "THICKNESS:" at 11407.23,5008.64 h60
  text "X" at 11945.4,5008.64 h60
  text "OTHER" at 13358.46,5008.64 h60
  text "TOLERANCE:" at 11407.23,4850.64 h60
  text "X" at 12246.53,4850.64 h60
  text "ANSI IPC-6012 TYPE 3 CLASS 2" at 12433.48,4850.64 h60
  text "OTHER +/-" at 12433.46,4694.64 h60
  text "BOW & TWIST:" at 11407.23,4537.64 h60
  text "X" at 12246.53,4537.64 h60
  text "ANSI IPC-6012 TYPE 3 CLASS 2" at 12433.48,4537.64 h60
  text "OTHER +/-" at 12433.46,4379.13 h60
  text "COPPER THICKNESS (FINISHED):" at 11332.46,4243.64 h60
  text "1.4MIL (1oz)" at 12212.46,4090.92 h60
  text "2MIL (1.4oz)" at 12979.46,4090.92 h60
  text "2.8MIL (2oz)" at 13706.46,4090.92 h60
  text "OUTER:" at 11689.46,4086.64 h60
  text "X" at 12084,4086 h60
  text "1.4MIL (1oz)" at 12212.46,3933.92 h60
  text "2.8MIL (2oz)" at 12979.46,3933.92 h60
  text "N/A" at 13706,3934.29 h60
  text "INNER SIGNAL:" at 11400.38,3929.64 h60
  text "X" at 12085.42,3929.64 h60
  text "DRILLING:" at 11332.46,3790.64 h60
  text "REFERENCE:" at 11407.23,3673.64 h60
  text "X" at 12055.46,3673.64 h60
  text "AS SHOWN" at 12242.46,3673.64 h60
  text "X" at 12956.46,3673.64 h60
  text "NC_DRILL FILES" at 13093.46,3673.64 h60
  text "PTH MIN COPPER THICKNESS:" at 11407.23,3515.64 h60
  text "X" at 12757.46,3515.64 h60
  text "1MIL" at 12894.46,3515.64 h60
  text "OTHER" at 13391.46,3515.64 h60
  text "BOARD FINISH:" at 11332.46,3356.64 h60
  text "SILKSCREEN:" at 11487.68,3238.64 h60
  text "X" at 12436.46,3238.64 h60
  text "TOP" at 12562.46,3238.64 h60
  text "X" at 12946.46,3238.64 h60
  text "BOTTOM" at 13073.46,3238.64 h60
  text "SILKSCREEN COLOR:" at 11486.01,3072.64 h60
  text "X" at 12433.75,3072.64 h60
  text "WHITE" at 12560.79,3072.64 h60
  text "OTHER" at 13071.79,3072.64 h60
  text "SOLDER RESIST COLOR:" at 11592.01,2921.64 h60
  text "GREEN" at 12286.79,2762.44 h60
  text "X" at 12049,2750 h60
  text "BLUE" at 12857,2744 h60
  text "OTHER" at 13306,2740 h60
  text "IMMERSION GOLD (ENIG)" at 12393.46,2553.92 h60
  text "ENEPIG" at 13731,2550.64 h60
  text "SURFACE FINISH:" at 11332.46,2549.64 h60
  text "X" at 12206.51,2549.64 h60
  text "IMM. TIN/SILVER OR EQUIV" at 11662,2392.64 h60
  text "OTHER" at 13093.46,2392.64 h60
  text "ARRAY/PANEL:" at 11332.46,2213.64 h60
  text "CUT AND TRIM PER MECH LAYER 1" at 12393.46,2209.35 h60
  text "N.C. ROUTE" at 12393.46,2057.64 h60
  text "X" at 13072.46,2057.64 h60
  text "V. SCORE" at 13259.46,2057.64 h60
  text "CERTIFICATION:" at 11332.46,1920.64 h60
  text "MATERIALS AND WORKMANSHIP FOR ALL PCBS" at 12057.46,1920.64 h60
  text "TO MEET OR EXCEED THE REQUIREMENTS OF:" at 12057.46,1822.64 h60
  text "X" at 11683.96,1686.13 h60
  text "ANSI IPC-A-600F CLASS ->" at 11822.96,1686.13 h60
  text "X" at 13462.02,1686.13 h60
  text "2" at 13580.96,1686.14 h60
  text "1" at 13265.96,1684.64 h60
  text "3" at 13934.96,1684.64 h60
  text "X" at 11686.02,1526.64 h60
  text "UL 94V-0" at 11822.96,1526.64 h60
  text "X" at 12498.02,1526.64 h60
  text "RoHS" at 12634.96,1526.64 h60
  text "OTHER" at 13279.36,1526.64 h60
  text "PER ORDER" at 13676.42,1526.64 h60
  text "ADDITIONAL REQUIREMENTS:" at 11332.46,1385.64 h60
  text "VIA TENTING:" at 12807,1292.36 h60
  text "X" at 13595.29,1292.48 h60
  text "YES" at 13378.67,1283.28 h60
  text "NO" at 13773.47,1283.05 h60
  text "MICROSECTION:" at 11407.23,1270.64 h60
  text "YES" at 12312.96,1270.64 h60
  text "REQUIRED" at 13174.46,1114.49 h60
  text "BARE BOARD ELEC. TEST:" at 11407.23,1111.64 h60
  text "NONE" at 12712.96,1111.64 h60
  text "X" at 13047.46,1111.64 h60
  text "PER ORDER" at 13766.46,1111.64 h60
  text "MANUFACTURER'S UL:" at 11407.23,954.64 h60
  text "RAIL" at 12572.96,950.35 h60
  text "METAL" at 13064.77,950.35 h60
  text "X" at 13440,950 h60
  text "SILK" at 13576.46,950.35 h60
M11 Gerber Information:
  lines w10: -292,-930.17 6308,-930.17 ; -292,-726.83 6310,-726.83 ; -292,-523.5 -292,-1133.5 3713,-1133.5 6310,-1133.5 6310,-523.5 -291.5,-523.5 -291.5,-1133.5 1284,-1133.5 ; 2173,-1133.5 2173,-523.5 ; 3690,-730 3690,-526.67 ; 4280,-726.83 4280,-523.5 ; 4902,-1140 4902,-937.17
  text "ALL ARTWORK VIEWED FROM TOP SIDE" at -228.5,-655.67 h60
  text "BOARD #:" at 2248,-655.67 h60
  text "SVN REV:" at 4476,-655.67 h60
  text ".VersionControl_RevNumber" at 4982,-655.67 h60
  text "REV: E1" at 3785,-657 h60
  text "TIDA-00110" at 2720,-660 h60
  text "LAYER NAME =" at -228.5,-858.49 h60
  text "PLOT NAME =" at -228.5,-1064.34 h60
  text ".plot_File_Name" at 577,-1064.34 h60
  text "GENERATED    :" at 2250,-1064.34 h60
  text ".Print_Date" at 3119.5,-1064.34 h60
  text ".Print_Time" at 3848.5,-1064.34 h60
  text "TEXAS INSTRUMENTS" at 5113,-1064.34 h60
M12 Stackup:
  lines w6: 11304,7657.5 14205,7657.5 ; 11304,7766 14205,7766 ; 11244,6974 ccw(c11279,6974) 11279,6939 14230,6939 ccw(c14230,6974) 14265,6974 14265,7858 ccw(c14230,7858) 14230,7893 11279,7893 ccw(c11279,7858) 11244,7858 11244,6974
  text "Layer Stack Up Detail for: TIDA-00110.PcbDoc" at 11304,7794.1 h48
  text "Layer" at 11304,7725.5 h25
  text "Gerber" at 12317.81,7725.5 h25
  text "Copper" at 12992.59,7725.5 h25
  text "Dielectric" at 13708.19,7725.5 h25
  text "Name" at 11304,7675.5 h25
  text "Document" at 12317.81,7675.5 h25
  text "Thickness" at 12992.59,7675.5 h25
  text "Material" at 13708.19,7675.5 h25
  text "Top Solder Mask" at 11304,7604.81 h35
  text "(.GTS)" at 12317.81,7604.81 h35
  text "Solder Resist" at 13708.19,7604.81 h35
  text "Top Layer" at 11304,7505.44 h35
  text "(.GTL)" at 12317.81,7505.44 h35
  text "1.4mil" at 12992.59,7505.44 h35
  text "FR-4" at 13708.19,7455.75 h35
  text "L2_GND-PLANE" at 11304,7406.06 h35
  text "(.G1)" at 12317.81,7406.06 h35
  text "1.4mil" at 12992.59,7406.06 h35
  text "FR-4" at 13708.19,7356.38 h35
  text "L3_PWR-PLANE" at 11304,7306.69 h35
  text "(.G2)" at 12317.81,7306.69 h35
  text "1.4mil" at 12992.59,7306.69 h35
  text "FR-4" at 13708.19,7257 h35
  text "Bottom Layer" at 11304,7207.31 h35
  text "(.GBL)" at 12317.81,7207.31 h35
  text "1.4mil" at 12992.59,7207.31 h35
  text "Bottom Solder Mask" at 11304,7107.94 h35
  text "(.GBS)" at 12317.81,7107.94 h35
  text "Solder Resist" at 13708.19,7107.94 h35
M13 Component Bodies Top:
  text ".Layer_Name" at 577,-858.49 h60
M14 Component Bodies Bottom:
  text ".Layer_Name" at 577,-858.49 h60
M15 Courtyards Top:
  text ".Layer_Name" at 577,-858.49 h60
M16 Courtyards Bottom:
  text ".Layer_Name" at 577,-858.49 h60
Drill Drawing:
  text ".legend" at 4281.25,609.45 h35
  text "DRILL TOLARENCE" at 4280,455 h60
  text "FOR PTH +/-3" at 4274,293 h60
  text "FOR 12MIL DRILL +0/-12MIL" at 4278,191 h60
  text "FOR 16MIL DRILL +0/-16MIL" at 4277,87 h60
  text "THIS IS NOT AN IMPEDENCE CONTROLLED BOARD" at 4263,-8 h60
  text ".Layer_Name" at 577,-858.49 h60

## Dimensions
0,0 to 3543.31,0 on Drill Drawing
0,0 to 0,1771.65 on Drill Drawing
